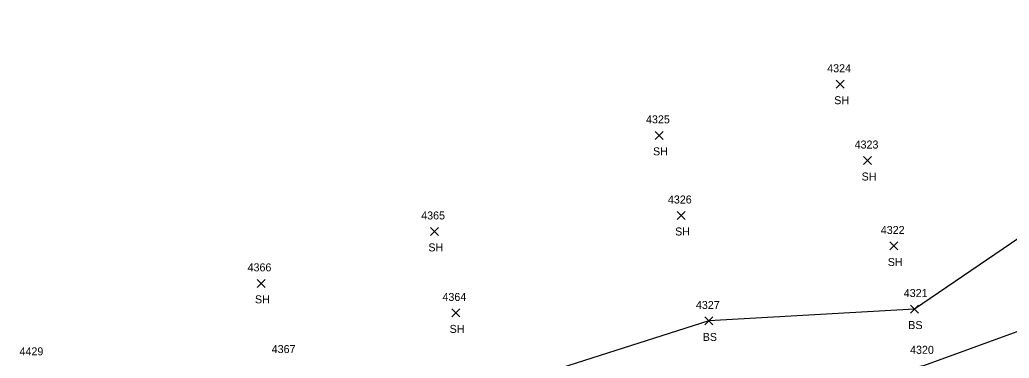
# Model space of a CAD drawing. Extents: x 1520648 to 1523413, y 732854 to 735518.
# Drawn here: x 1520648.4 to 1520895.7, y 733487 to 733571.7 of the extents above; entities that cross this region are included whole.
import ezdxf

# ---------------------------------------------------------------- set-up
doc = ezdxf.new("R2010")
doc.units = 0
for name, color, linetype in [('L_A', 7, 'Continuous'), ('L_I', 7, 'Continuous'), ('L_TIC', 7, 'Continuous'), ('LELB', 7, 'Continuous')]:
    doc.layers.add(name, color=color, linetype=linetype)

msp = doc.modelspace()

# ---------------------------------------------------------------- linework, layer by layer
at = {"layer": 'L_TIC'}
for points in [[(1520852.48, 733554.56), (1520854.48, 733556.56)], [(1520854.48, 733554.56), (1520852.48, 733556.56)], [(1520807.2, 733541.77), (1520809.2, 733543.77)], [(1520809.2, 733541.77), (1520807.2, 733543.77)], [(1520859.33, 733535.47), (1520861.33, 733537.47)], [(1520861.33, 733535.47), (1520859.33, 733537.47)], [(1520812.73, 733521.72), (1520814.73, 733523.72)], [(1520814.73, 733521.72), (1520812.73, 733523.72)], [(1520751.06, 733517.73), (1520753.06, 733519.73)], [(1520753.06, 733517.73), (1520751.06, 733519.73)], [(1520865.87, 733514.09), (1520867.87, 733516.09)], [(1520867.87, 733514.09), (1520865.87, 733516.09)], [(1520707.73, 733504.74), (1520709.73, 733506.74)], [(1520709.73, 733504.74), (1520707.73, 733506.74)], [(1520756.38, 733497.34), (1520758.38, 733499.34)], [(1520758.38, 733497.34), (1520756.38, 733499.34)], [(1520871.04, 733498.31), (1520873.04, 733500.31)], [(1520873.04, 733498.31), (1520871.04, 733500.31)], [(1520819.67, 733495.33), (1520821.67, 733497.33)], [(1520821.67, 733495.33), (1520819.67, 733497.33)]]:
    msp.add_lwpolyline(points, dxfattribs=at)
at = {"layer": 'LELB'}
for points in [[(1520924.94, 733571.69), (1520931.25, 733539.14), (1520932.11, 733517.28), (1520920.03, 733501.75), (1520874.27, 733485.11), (1520825.89, 733476.63), (1520766.38, 733461.59), (1520726.01, 733448.53), (1520664.21, 733429.23)], [(1520912.95, 733567.21), (1520918.33, 733540.81), (1520912.15, 733526.62), (1520872.04, 733499.31), (1520820.67, 733496.33), (1520762.19, 733477.66), (1520720.67, 733466.78), (1520660.6, 733449.58)]]:
    msp.add_lwpolyline(points, dxfattribs=at)

# ---------------------------------------------------------------- texts
at = {"layer": 'L_A'}
for s, p in [('SH', (1520851.97, 733550.56)), ('SH', (1520806.69, 733537.77)), ('SH', (1520858.82, 733531.47)), ('SH', (1520812.22, 733517.72)), ('SH', (1520750.55, 733513.73)), ('SH', (1520865.36, 733510.09)), ('SH', (1520707.22, 733500.74)), ('BS', (1520870.48, 733494.31)), ('SH', (1520755.86, 733493.34)), ('BS', (1520819.11, 733491.33))]:
    msp.add_text(s, height=2, dxfattribs=at).set_placement(p)
at = {"layer": 'L_I'}
for s, p in [('4324', (1520850.22, 733558.56)), ('4325', (1520804.94, 733545.77)), ('4323', (1520857.07, 733539.47)), ('4326', (1520810.41, 733525.72)), ('4365', (1520748.76, 733521.73)), ('4322', (1520863.61, 733518.09)), ('4366', (1520705.37, 733508.74)), ('4364', (1520754.07, 733501.34)), ('4321', (1520869.35, 733502.31)), ('4327', (1520817.41, 733499.33)), ('4429', (1520648.38, 733487.73)), ('4367', (1520711.4, 733488.3)), ('4320', (1520870.93, 733488.11))]:
    msp.add_text(s, height=2, dxfattribs=at).set_placement(p)

doc.saveas('drawing.dxf')
